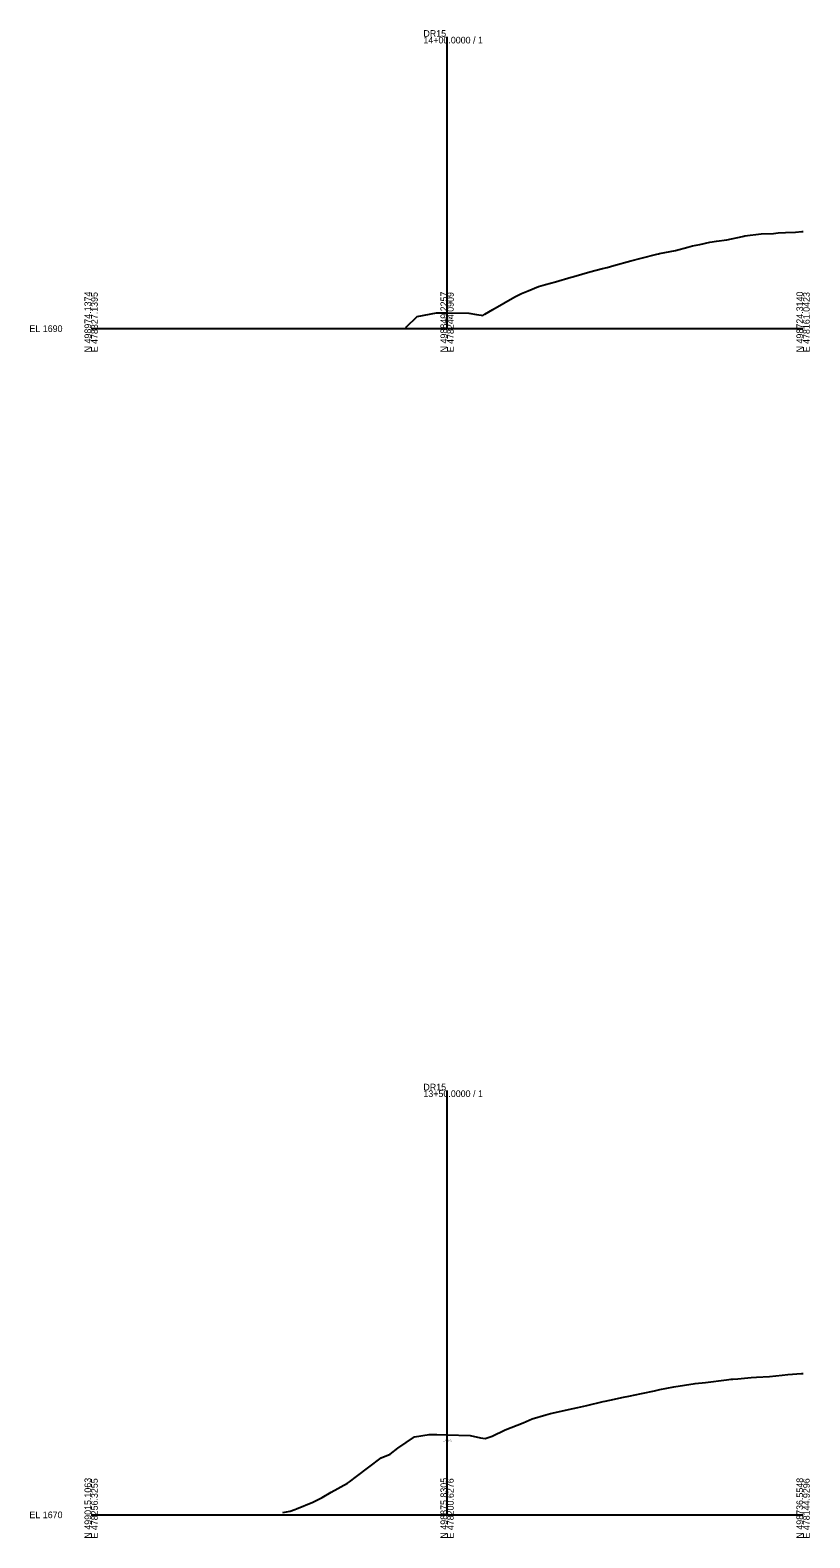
# Model space of a CAD drawing. Extents: x -26 to 303, y -10 to 4126.
# Drawn here: x -26 to 303, y 3490 to 4126 of the extents above; entities that cross this region are included whole.
import ezdxf

# ---------------------------------------------------------------- set-up
doc = ezdxf.new("R2010")
doc.units = 0
for name, color, linetype in [('Exist Cross Section Cell', 7, 'Continuous'), ('Exist XS Center Line Elevation Label', 7, 'Continuous'), ('Exist XS Ground Line', 7, 'Continuous')]:
    doc.layers.add(name, color=color, linetype=linetype)

msp = doc.modelspace()

# ---------------------------------------------------------------- linework, layer by layer
at = {"layer": 'Exist Cross Section Cell'}
for p, q in [((150, 4000), (150, 4123)), ((0, 4000), (150, 4000)), ((150, 4000), (300, 4000)), ((150, 3500), (150, 3678.91)), ((0, 3500), (150, 3500)), ((150, 3500), (300, 3500))]:
    msp.add_line(p, q, dxfattribs=at)
at = {"layer": 'Exist XS Ground Line'}
for points in [[(132.48, 4000.79), (132.71, 4000.61), (137.4, 4005.16), (145.49, 4006.68), (150, 4006.62), (159.09, 4006.52), (162.32, 4005.92), (164.34, 4005.6), (164.99, 4005.53), (165.89, 4006.04), (169.21, 4008.06), (178.58, 4013.34), (181.3, 4014.79), (184.16, 4015.96), (188.51, 4017.72), (191.41, 4018.6), (195.73, 4019.76), (202.23, 4021.62), (202.94, 4021.81), (203.42, 4021.93), (210.16, 4023.91), (215.43, 4025.31), (217.37, 4025.77), (220.29, 4026.62), (227.44, 4028.6), (231.8, 4029.71), (238.36, 4031.37), (239.01, 4031.52), (239.45, 4031.62), (246.23, 4032.94), (251.46, 4034.27), (253.44, 4034.84), (256.42, 4035.5), (260.66, 4036.38), (263.47, 4036.79), (267.87, 4037.42), (274.49, 4038.87), (275.08, 4038.98), (275.48, 4039.06), (282.3, 4039.9), (287.49, 4040.16), (289.51, 4040.37), (292.55, 4040.53), (296.73, 4040.69), (299.5, 4040.95), (300, 4041)], [(80.76, 3500.99), (83.88, 3501.51), (85.77, 3502.22), (86.52, 3502.51), (93.46, 3505.33), (97.3, 3507.32), (101.16, 3509.63), (108.07, 3513.41), (108.85, 3513.94), (111.88, 3516.14), (122.19, 3524.07), (125.96, 3525.59), (129.27, 3528.16), (136.29, 3532.91), (142.44, 3533.86), (143.51, 3533.93), (145.65, 3533.89), (150, 3533.75), (159.78, 3533.44), (164.03, 3532.48), (166.01, 3532.16), (169.01, 3533.17), (174.44, 3535.77), (181.99, 3538.85), (185.8, 3540.44), (191.63, 3542.13), (193.5, 3542.71), (194.25, 3542.88), (201.19, 3544.37), (205.02, 3545.2), (208.89, 3546.11), (215.79, 3547.77), (216.58, 3547.96), (218.57, 3548.37), (224.28, 3549.58), (226.56, 3550.02), (231.97, 3551.17), (237.33, 3552.34), (239.67, 3552.86), (245.5, 3553.93), (254.53, 3555.34), (258.88, 3555.8), (267.79, 3556.88), (269.65, 3557.14), (270.45, 3557.19), (272.44, 3557.38), (278.14, 3557.87), (280.42, 3558.04), (285.84, 3558.33), (291.19, 3558.89), (293.53, 3559.15), (299.37, 3559.6), (300, 3559.64)]]:
    msp.add_lwpolyline(points, dxfattribs=at)

# ---------------------------------------------------------------- texts
at = {"layer": 'Exist Cross Section Cell'}
for s, p in [('DR15', (140, 4123)), ('14+00.0000 / 1', (140, 4120.2)), ('EL 1690', (-26, 3998.6)), ('DR15', (140, 3678.91)), ('13+50.0000 / 1', (140, 3676.11)), ('EL 1670', (-26, 3498.6))]:
    msp.add_text(s, height=2.8, dxfattribs=at).set_placement(p)
for s, p in [('N 498974.1374', (0, 3990)), ('E 478327.1395', (2.8, 3990)), ('N 498849.2257', (150, 3990)), ('E 478244.0909', (152.8, 3990)), ('N 498724.3140', (300, 3990)), ('E 478161.0423', (302.8, 3990)), ('N 499015.1063', (0, 3490)), ('E 478256.3255', (2.8, 3490)), ('N 498875.8305', (150, 3490)), ('E 478200.6276', (152.8, 3490)), ('N 498736.5548', (300, 3490)), ('E 478144.9296', (302.8, 3490))]:
    msp.add_text(s, height=2.8, rotation=90, dxfattribs=at).set_placement(p)
at = {"layer": 'Exist XS Center Line Elevation Label'}
for s, p in [('1696.62', (148.26, 4003.87)), ('1703.75', (148.26, 3531))]:
    msp.add_text(s, height=0.75, dxfattribs=at).set_placement(p)

doc.saveas('drawing.dxf')
